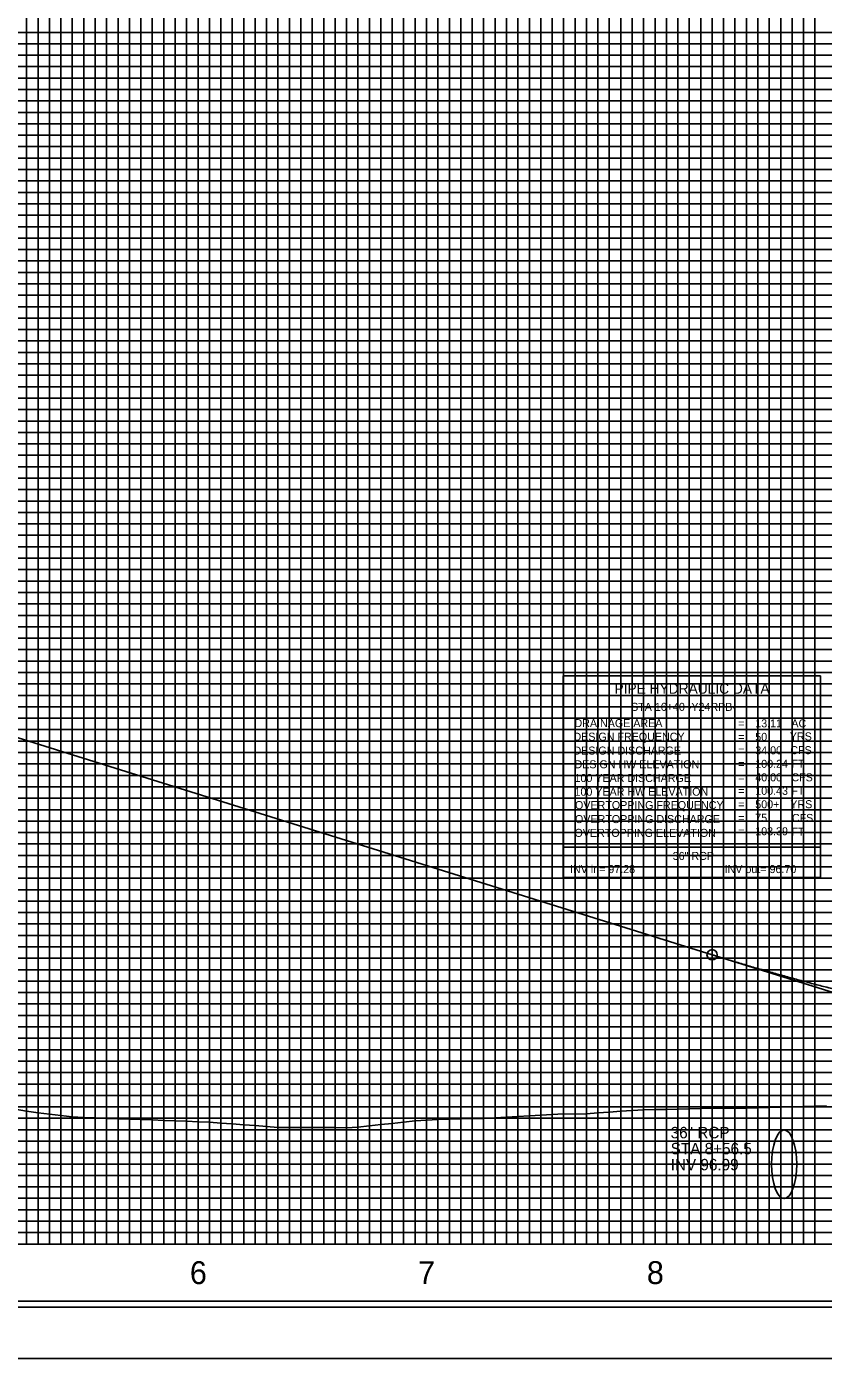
# Model space of a CAD drawing. Extents: x 2345490 to 2436403, y 465165 to 573888.
# Drawn here: x 2411420 to 2411769, y 532446 to 533028 of the extents above; entities that cross this region are included whole.
import ezdxf

# ---------------------------------------------------------------- set-up
doc = ezdxf.new("R2010")
doc.units = 0
for name, color, linetype in [('Old_Level_1', 7, 'Continuous'), ('Old_Level_18', 7, 'Continuous'), ('Old_Level_2', 7, 'Continuous'), ('Old_Level_3', 7, 'Continuous'), ('Old_Level_4', 7, 'Continuous'), ('Old_Level_41', 7, 'Continuous'), ('Old_Level_42', 7, 'Continuous'), ('Old_Level_43', 7, 'Continuous'), ('Old_Level_50', 7, 'Continuous'), ('Old_Level_51', 7, 'Continuous'), ('Old_Level_62', 7, 'Continuous'), ('Old_Level_63', 7, 'Continuous')]:
    doc.layers.add(name, color=color, linetype=linetype)

msp = doc.modelspace()

# ---------------------------------------------------------------- linework, layer by layer
at = {"layer": 'Old_Level_1'}
msp.add_lwpolyline([(2411415.325, 532554.5325), (2411420.325, 532553.721), (2411425.325, 532552.97475), (2411430.325, 532552.40075), (2411435.325, 532551.81875), (2411440.325, 532551.229), (2411445.325, 532550.97375), (2411450.325, 532550.775), (2411455.325, 532550.573), (2411460.325, 532550.40375), (2411465.325, 532550.2425), (2411470.325, 532550.08), (2411475.325, 532549.899), (2411480.325, 532549.6895), (2411485.325, 532549.47875), (2411490.325, 532549.267), (2411495.325, 532549.0545), (2411500.325, 532548.841), (2411505.325, 532548.5345), (2411510.325, 532548.15575), (2411515.325, 532547.7745), (2411520.325, 532547.3915), (2411525.325, 532547.00675), (2411530.325, 532546.61925), (2411535.325, 532546.5155), (2411540.325, 532546.5295), (2411545.325, 532546.53425), (2411550.325, 532546.5295), (2411555.325, 532546.5155), (2411560.325, 532546.49225), (2411565.325, 532546.69175), (2411570.325, 532547.2545), (2411575.325, 532547.81), (2411580.325, 532548.3575), (2411585.325, 532548.90975), (2411590.325, 532549.5275), (2411595.325, 532549.82975), (2411600.325, 532549.99525), (2411605.325, 532550.157), (2411610.325, 532550.3155), (2411615.325, 532550.47), (2411620.325, 532550.56225), (2411625.325, 532550.7335), (2411630.325, 532551.05875), (2411635.325, 532551.37725), (2411640.325, 532551.68875), (2411645.325, 532551.97725), (2411650.325, 532552.2585), (2411655.325, 532552.49725), (2411660.325, 532552.409), (2411665.325, 532552.5415), (2411670.325, 532552.9175), (2411675.325, 532553.29275), (2411680.325, 532553.662), (2411685.325, 532554.017), (2411690.325, 532554.2725), (2411695.325, 532554.369), (2411700.325, 532554.46675), (2411705.325, 532554.57525), (2411710.325, 532554.72675), (2411715.325, 532554.874), (2411720.325, 532555.017), (2411725.325, 532555.09625), (2411730.325, 532554.9455), (2411735.325, 532555.056), (2411740.325, 532555.1905), (2411745.325, 532555.32875), (2411750.325, 532555.4705), (2411755.325, 532555.616), (2411760.325, 532555.76475), (2411765.325, 532555.92575), (2411770.325, 532556.10975)], dxfattribs=at)
at = {"layer": 'Old_Level_18'}
msp.add_lwpolyline([(2412345.325, 533520.5875), (2410845.325, 533520.5875), (2410845.325, 532470.5875), (2412345.325, 532470.5875)], close=True, dxfattribs=at)
at = {"layer": 'Old_Level_2'}
for p, q in [((2411220.325, 532778.261), (2411720.325, 532622.1275)), ((2411720.325, 532622.1275), (2411867.70025, 532576.10725))]:
    msp.add_line(p, q, dxfattribs=at)
msp.add_circle((2411720.325, 532622.1275), 2.25, dxfattribs=at)
msp.add_spline([(2411720.325, 532622.1275), (2411726.325, 532620.2745), (2411732.325, 532618.46275), (2411738.325, 532616.692), (2411744.325, 532614.9625), (2411750.325, 532613.27425), (2411756.325, 532611.62725), (2411762.325, 532610.02125), (2411768.325, 532608.45625), (2411774.325, 532606.93275), (2411780.325, 532605.45025), (2411786.325, 532604.009), (2411792.325, 532602.609), (2411798.325, 532601.25), (2411804.325, 532599.93225), (2411810.325, 532598.6555), (2411816.325, 532597.42025), (2411822.325, 532596.226), (2411828.325, 532595.07275), (2411834.325, 532593.961), (2411840.325, 532592.89025), (2411846.325, 532591.86075), (2411852.325, 532590.87225), (2411858.325, 532589.925), (2411864.325, 532589.019), (2411870.325, 532588.15425), (2411876.325, 532587.3305), (2411882.325, 532586.548), (2411888.325, 532585.80675), (2411894.325, 532585.1065), (2411900.325, 532584.4475), (2411906.325, 532583.82975), (2411912.325, 532583.253), (2411918.325, 532582.7175), (2411924.325, 532582.22325), (2411930.325, 532581.77025), (2411936.325, 532581.35825), (2411942.325, 532580.9875), (2411948.325, 532580.65775), (2411954.325, 532580.3695), (2411960.325, 532580.12225), (2411966.325, 532579.916), (2411972.325, 532579.75125), (2411978.325, 532579.6275), (2411984.325, 532579.54475), (2411990.325, 532579.5035), (2411996.325, 532579.50325), (2412002.325, 532579.54425), (2412008.325, 532579.62625), (2412014.325, 532579.7495), (2412020.325, 532579.914)], degree=3, dxfattribs=at)
at = {"layer": 'Old_Level_3'}
msp.add_ellipse((2411751.825, 532530.4875), major_axis=(0, 15), ratio=0.366306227, dxfattribs=at)
at = {"layer": 'Old_Level_4'}
for p, q in [((2411655.18793, 532744.141), (2411767.68793, 532744.141)), ((2411655.18793, 532669.141), (2411655.18793, 532744.141)), ((2411767.68793, 532744.141), (2411767.68793, 532669.141)), ((2411767.68793, 532669.141), (2411655.18793, 532669.141))]:
    msp.add_line(p, q, dxfattribs=at)
msp.add_lwpolyline([(2411655.18793, 532669.141), (2411767.68793, 532669.141), (2411767.68793, 532655.926), (2411655.18793, 532655.926)], close=True, dxfattribs=at)
at = {"layer": 'Old_Level_41'}
msp.add_line((2412345.325, 532495.5875), (2410845.325, 532495.5875), dxfattribs=at)
for points in [[(2411370.325, 532495.5875), (2411420.325, 532495.5875), (2411420.325, 533520.5875)], [(2411395.325, 532495.5875), (2411445.325, 532495.5875), (2411445.325, 533520.5875)], [(2411470.325, 533520.5875), (2411470.325, 532495.5875), (2411520.325, 532495.5875), (2411520.325, 533520.5875)], [(2411495.325, 533520.5875), (2411495.325, 532495.5875), (2411545.325, 532495.5875), (2411545.325, 533520.5875)], [(2411570.325, 533520.5875), (2411570.325, 532495.5875), (2411620.325, 532495.5875), (2411620.325, 533520.5875)], [(2411595.325, 533520.5875), (2411595.325, 532495.5875), (2411645.325, 532495.5875), (2411645.325, 533520.5875)], [(2411670.325, 533520.5875), (2411670.325, 532495.5875), (2411720.325, 532495.5875), (2411720.325, 533520.5875)], [(2411695.325, 533520.5875), (2411695.325, 532495.5875), (2411745.325, 532495.5875), (2411745.325, 533520.5875)], [(2412345.325, 533020.5875), (2410845.325, 533020.5875), (2410845.325, 532970.5875), (2412345.325, 532970.5875)], [(2412345.325, 532920.5875), (2410845.325, 532920.5875), (2410845.325, 532870.5875), (2412345.325, 532870.5875)], [(2412345.325, 532845.5875), (2410845.325, 532845.5875), (2410845.325, 532895.5875), (2412345.325, 532895.5875)], [(2412345.325, 532820.5875), (2410845.325, 532820.5875), (2410845.325, 532770.5875), (2412345.325, 532770.5875)], [(2412345.325, 532745.5875), (2410845.325, 532745.5875), (2410845.325, 532795.5875), (2412345.325, 532795.5875)], [(2412345.325, 532720.5875), (2410845.325, 532720.5875), (2410845.325, 532670.5875), (2412345.325, 532670.5875)], [(2412345.325, 532620.5875), (2410845.325, 532620.5875), (2410845.325, 532570.5875), (2412345.325, 532570.5875)], [(2412345.325, 532545.5875), (2410845.325, 532545.5875), (2410845.325, 532595.5875), (2412345.325, 532595.5875)], [(2412345.325, 532520.5875), (2410845.325, 532520.5875)]]:
    msp.add_lwpolyline(points, dxfattribs=at)
at = {"layer": 'Old_Level_42'}
for points in [[(2412345.325, 532945.5875), (2410845.325, 532945.5875), (2410845.325, 532995.5875), (2412345.325, 532995.5875)], [(2412345.325, 532645.5875), (2410845.325, 532645.5875), (2410845.325, 532695.5875), (2412345.325, 532695.5875)]]:
    msp.add_lwpolyline(points, dxfattribs=at)
at = {"layer": 'Old_Level_43'}
for points in [[(2411425.325, 532495.5875), (2411425.325, 533520.5875)], [(2411430.325, 533520.5875), (2411430.325, 532495.5875), (2411435.325, 532495.5875), (2411435.325, 533520.5875)], [(2411440.325, 533520.5875), (2411440.325, 532495.5875), (2411450.325, 532495.5875), (2411450.325, 533520.5875)], [(2411455.325, 533520.5875), (2411455.325, 532495.5875), (2411455.325, 532495.5875), (2411460.325, 532495.5875), (2411460.325, 533520.5875)], [(2411465.325, 533520.5875), (2411465.325, 532495.5875), (2411475.325, 532495.5875), (2411475.325, 533520.5875)], [(2411480.325, 533520.5875), (2411480.325, 532495.5875), (2411485.325, 532495.5875), (2411485.325, 533520.5875)], [(2411490.325, 533520.5875), (2411490.325, 532495.5875), (2411500.325, 532495.5875), (2411500.325, 533520.5875)], [(2411505.325, 533520.5875), (2411505.325, 532495.5875), (2411510.325, 532495.5875), (2411510.325, 533520.5875)], [(2411515.325, 533520.5875), (2411515.325, 532495.5875), (2411525.325, 532495.5875), (2411525.325, 533520.5875)], [(2411530.325, 533520.5875), (2411530.325, 532495.5875), (2411535.325, 532495.5875), (2411535.325, 533520.5875)], [(2411540.325, 533520.5875), (2411540.325, 532495.5875), (2411550.325, 532495.5875), (2411550.325, 533520.5875)], [(2411555.325, 533520.5875), (2411555.325, 532495.5875), (2411560.325, 532495.5875), (2411560.325, 533520.5875)], [(2411565.325, 533520.5875), (2411565.325, 532495.5875), (2411575.325, 532495.5875), (2411575.325, 533520.5875)], [(2411580.325, 533520.5875), (2411580.325, 532495.5875), (2411585.325, 532495.5875), (2411585.325, 533520.5875)], [(2411590.325, 533520.5875), (2411590.325, 532495.5875), (2411600.325, 532495.5875), (2411600.325, 533520.5875)], [(2411605.325, 533520.5875), (2411605.325, 532495.5875)], [(2411605.325, 532495.5875), (2411610.325, 532495.5875), (2411610.325, 533519.9875)], [(2411615.325, 533519.9875), (2411615.325, 532495.5875), (2411625.325, 532495.5875), (2411625.325, 533520.5875)], [(2411630.325, 533520.5875), (2411630.325, 532495.5875), (2411635.325, 532495.5875), (2411635.325, 533520.5875)], [(2411640.325, 533520.5875), (2411640.325, 532495.5875), (2411650.325, 532495.5875), (2411650.325, 533520.5875)], [(2411655.325, 533520.5875), (2411655.325, 532495.5875), (2411660.325, 532495.5875), (2411660.325, 533520.5875)], [(2411665.325, 533520.5875), (2411665.325, 532495.5875), (2411675.325, 532495.5875), (2411675.325, 533520.5875)], [(2411680.325, 533520.5875), (2411680.325, 532495.5875), (2411685.325, 532495.5875), (2411685.325, 533520.5875)], [(2411690.325, 533520.5875), (2411690.325, 532495.5875), (2411700.325, 532495.5875), (2411700.325, 533520.5875)], [(2411705.325, 533520.5875), (2411705.325, 532495.5875), (2411710.325, 532495.5875), (2411710.325, 533520.5875)], [(2411715.325, 533520.5875), (2411715.325, 532495.5875), (2411725.325, 532495.5875), (2411725.325, 533520.5875)], [(2411730.325, 533520.5875), (2411730.325, 532495.5875), (2411735.325, 532495.5875), (2411735.325, 533520.5875)], [(2411740.325, 533520.5875), (2411740.325, 532495.5875), (2411750.325, 532495.5875), (2411750.325, 533520.5875)], [(2411755.325, 533520.5875), (2411755.325, 532495.5875), (2411760.325, 532495.5875), (2411760.325, 533520.5875)], [(2411765.325, 533520.5875), (2411765.325, 532495.5875), (2411775.325, 532495.5875), (2411775.325, 533520.5875)], [(2412295.325, 533025.5875), (2410895.325, 533025.5875), (2410895.325, 533015.5875), (2412295.325, 533015.5875)], [(2412295.325, 533010.5875), (2410895.325, 533010.5875), (2410895.325, 533005.5875), (2412295.325, 533005.5875)], [(2412295.325, 533000.5875), (2410895.325, 533000.5875)], [(2410895.325, 532990.5875), (2412295.325, 532990.5875)], [(2412295.325, 532985.5875), (2410895.325, 532985.5875), (2410895.325, 532980.5875), (2412295.325, 532980.5875)], [(2412295.325, 532975.5875), (2410895.325, 532975.5875), (2410895.325, 532965.5875), (2412295.325, 532965.5875)], [(2412295.325, 532960.5875), (2410895.325, 532960.5875), (2410895.325, 532955.5875), (2412295.325, 532955.5875)], [(2412295.325, 532950.5875), (2410895.325, 532950.5875), (2410895.325, 532940.5875), (2412295.325, 532940.5875)], [(2412295.325, 532935.5875), (2410895.325, 532935.5875), (2410895.325, 532930.5875), (2412295.325, 532930.5875)], [(2412295.325, 532925.5875), (2410895.325, 532925.5875), (2410895.325, 532915.5875), (2412295.325, 532915.5875)], [(2412295.325, 532910.5875), (2410895.325, 532910.5875), (2410895.325, 532905.5875), (2412295.325, 532905.5875)], [(2412295.325, 532900.5875), (2410895.325, 532900.5875), (2410895.325, 532890.5875), (2412295.325, 532890.5875)], [(2412295.325, 532885.5875), (2410895.325, 532885.5875), (2410895.325, 532880.5875), (2412295.325, 532880.5875)], [(2412295.325, 532875.5875), (2410895.325, 532875.5875), (2410895.325, 532865.5875), (2412295.325, 532865.5875)], [(2412295.325, 532860.5875), (2410895.325, 532860.5875), (2410895.325, 532855.5875), (2412295.325, 532855.5875)], [(2412295.325, 532850.5875), (2410895.325, 532850.5875), (2410895.325, 532840.5875), (2412295.325, 532840.5875)], [(2412295.325, 532835.5875), (2410895.325, 532835.5875), (2410895.325, 532830.5875), (2412295.325, 532830.5875)], [(2412295.325, 532825.5875), (2410895.325, 532825.5875), (2410895.325, 532815.5875), (2412295.325, 532815.5875)], [(2412295.325, 532810.5875), (2410895.325, 532810.5875), (2410895.325, 532805.5875), (2412295.325, 532805.5875)], [(2412295.325, 532800.5875), (2410895.325, 532800.5875), (2410895.325, 532790.5875), (2412295.325, 532790.5875)], [(2412295.325, 532785.5875), (2410895.325, 532785.5875), (2410895.325, 532780.5875), (2412295.325, 532780.5875)], [(2412295.325, 532775.5875), (2410895.325, 532775.5875), (2410895.325, 532765.5875), (2412295.325, 532765.5875)], [(2412295.325, 532760.5875), (2410895.325, 532760.5875), (2410895.325, 532755.5875), (2412295.325, 532755.5875)], [(2412295.325, 532750.5875), (2410895.325, 532750.5875), (2410895.325, 532740.5875), (2412295.325, 532740.5875)], [(2412295.325, 532735.5875), (2410895.325, 532735.5875), (2410895.325, 532730.5875), (2412295.325, 532730.5875)], [(2412295.325, 532725.5875), (2410895.325, 532725.5875), (2410895.325, 532715.5875), (2412295.325, 532715.5875)], [(2412295.325, 532710.5875), (2410895.325, 532710.5875), (2410895.325, 532705.5875), (2412295.325, 532705.5875)], [(2412295.325, 532700.5875), (2410895.325, 532700.5875)], [(2410895.325, 532690.5875), (2412295.325, 532690.5875)], [(2412295.325, 532685.5875), (2410895.325, 532685.5875), (2410895.325, 532680.5875), (2412295.325, 532680.5875)], [(2412295.325, 532675.5875), (2410895.325, 532675.5875)], [(2410895.325, 532665.5875), (2412295.325, 532665.5875)], [(2412295.325, 532660.5875), (2410895.325, 532660.5875), (2410895.325, 532655.5875), (2412295.325, 532655.5875)], [(2412295.325, 532650.5875), (2410895.325, 532650.5875), (2410895.325, 532640.5875), (2412295.325, 532640.5875)], [(2412295.325, 532635.5875), (2410895.325, 532635.5875), (2410895.325, 532630.5875), (2412295.325, 532630.5875)], [(2412295.325, 532625.5875), (2410895.325, 532625.5875), (2410895.325, 532615.5875), (2412295.325, 532615.5875)], [(2412295.325, 532610.5875), (2410895.325, 532610.5875), (2410895.325, 532605.5875), (2412295.325, 532605.5875)], [(2412295.325, 532600.5875), (2410895.325, 532600.5875), (2410895.325, 532590.5875), (2412295.325, 532590.5875)], [(2412295.325, 532585.5875), (2410895.325, 532585.5875), (2410895.325, 532580.5875), (2412295.325, 532580.5875)], [(2412295.325, 532575.5875), (2410895.325, 532575.5875), (2410895.325, 532565.5875), (2412295.325, 532565.5875)], [(2412295.325, 532560.5875), (2410895.325, 532560.5875), (2410895.325, 532555.5875), (2412295.325, 532555.5875)], [(2412295.325, 532550.5875), (2410895.325, 532550.5875), (2410895.325, 532540.5875), (2412295.325, 532540.5875)], [(2412295.325, 532535.5875), (2410895.325, 532535.5875), (2410895.325, 532530.5875), (2412295.325, 532530.5875)], [(2412295.325, 532525.5875), (2410895.325, 532525.5875), (2410895.325, 532515.5875), (2412295.325, 532515.5875)], [(2412295.325, 532510.5875), (2410895.325, 532510.5875), (2410895.325, 532505.5875), (2412295.325, 532505.5875)], [(2412295.325, 532500.5875), (2410895.325, 532500.5875)]]:
    msp.add_lwpolyline(points, dxfattribs=at)
at = {"layer": 'Old_Level_50'}
msp.add_lwpolyline([(2412357.825, 533523.1375), (2410691.325, 533523.1375), (2410691.325, 532468.0375), (2412357.825, 532468.0375)], close=True, dxfattribs=at)
at = {"layer": 'Old_Level_51'}
msp.add_lwpolyline([(2412362.325, 533545.5875), (2410678.325, 533545.5875), (2410678.325, 532445.5875), (2412362.325, 532445.5875)], close=True, dxfattribs=at)
at = {"layer": 'Old_Level_63'}
msp.add_line((2410895.325, 532495.5875), (2412059.1905, 532495.5875), dxfattribs=at)

# ---------------------------------------------------------------- texts
at = {"layer": 'Old_Level_3'}
for s, p in [('36" RCP', (2411702.18437, 532541.83139)), ('STA 8+56.5', (2411702.18437, 532534.83139)), ('INV 96.99', (2411702.18437, 532527.83139))]:
    msp.add_text(s, height=4.999999, rotation=0.00003889, dxfattribs=at).set_placement(p)
at = {"layer": 'Old_Level_4'}
for s, height, p in [('PIPE HYDRAULIC DATA', 4.49985, (2411677.58793, 532736.316)), ('STA 16+40 -Y24RPB-', 3.4998, (2411684.84143, 532728.81575)), ('DRAINAGE AREA', 3.49995, (2411660.08793, 532721.691)), ('=        ', 3.49995, (2411731.73793, 532721.591)), ('13.11', 3.49995, (2411739.19843, 532721.5905)), ('AC', 3.49995, (2411755.01293, 532721.591)), ('DESIGN FREQUENCY', 3.49995, (2411659.63793, 532715.766)), ('=        ', 3.49995, (2411731.73793, 532715.691)), ('50', 3.49995, (2411739.19843, 532715.6905)), ('YRS', 3.49995, (2411754.31293, 532715.891)), ('DESIGN DISCHARGE', 3.49995, (2411659.63793, 532709.691)), ('=        ', 3.49995, (2411731.73793, 532709.791)), ('34.00', 3.49995, (2411739.19843, 532709.7905)), ('CFS', 3.49995, (2411754.53793, 532709.866)), ('DESIGN HW ELEVATION', 3.49995, (2411660.08793, 532703.691)), ('=        ', 3.49995, (2411731.73793, 532703.891)), ('100.24', 3.49995, (2411739.19843, 532703.8905)), ('FT', 3.49995, (2411755.01293, 532703.891)), ('100 YEAR DISCHARGE', 3.49995, (2411660.08793, 532697.691)), ('=        ', 3.49995, (2411731.73793, 532697.991)), ('40.00', 3.49995, (2411739.19843, 532697.9905)), ('CFS', 3.49995, (2411755.01293, 532697.991)), ('100 YEAR HW ELEVATION', 3.49995, (2411660.08793, 532691.691)), ('=        ', 3.49995, (2411731.73793, 532692.091)), ('100.43', 3.49995, (2411739.19843, 532692.09075)), ('FT', 3.49995, (2411755.01293, 532692.091)), ('OVERTOPPING FREQUENCY', 3.49995, (2411660.31293, 532685.841)), ('=        ', 3.49995, (2411731.73793, 532686.191)), ('500+', 3.49995, (2411739.19843, 532686.19075)), ('YRS', 3.49995, (2411754.53793, 532686.241)), ('OVERTOPPING DISCHARGE', 3.49995, (2411660.31293, 532679.716)), ('=        ', 3.49995, (2411731.73793, 532680.291)), ('75', 3.49995, (2411739.19843, 532680.29075)), ('CFS', 3.49995, (2411755.23793, 532680.216)), ('OVERTOPPING ELEVATION', 3.49995, (2411660.08793, 532673.691)), ('=        ', 3.49995, (2411731.73793, 532674.391)), ('103.39', 3.49995, (2411739.19843, 532674.39075)), ('FT', 3.49995, (2411755.01293, 532674.191)), ('36" RCP', 3.4998, (2411703.07193, 532663.60025)), ('INV in= 97.28', 3.4998, (2411658.12043, 532657.853)), ('INV out= 96.70', 3.4998, (2411725.79718, 532657.853))]:
    msp.add_text(s, height=height, dxfattribs=at).set_placement(p)
at = {"layer": 'Old_Level_62'}
for s, p in [('6', (2411491.7645, 532478.0875)), ('7', (2411591.622, 532478.0875)), ('8', (2411691.748, 532478.0875))]:
    msp.add_text(s, height=10, dxfattribs=at).set_placement(p)

doc.saveas('drawing.dxf')
